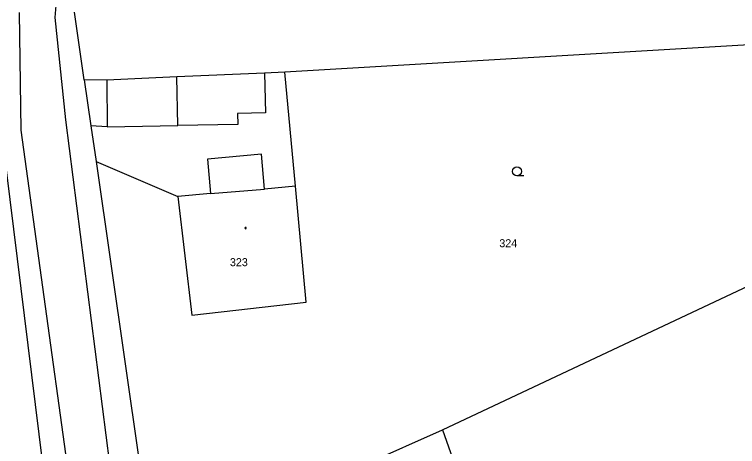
# Model space of a CAD drawing. Extents: x -454285 to -453563, y -1108687 to -1108249.
# Drawn here: x -454141.3 to -454078.1, y -1108501.4 to -1108463.6 of the extents above; entities that cross this region are included whole.
import ezdxf

# ---------------------------------------------------------------- set-up
doc = ezdxf.new("R2010")
doc.units = 0
for name, color, linetype in [('1', 7, 'Continuous'), ('14', 7, 'Continuous'), ('15', 7, 'Continuous'), ('2', 7, 'Continuous'), ('23', 7, 'Continuous'), ('25', 7, 'Continuous')]:
    doc.layers.add(name, color=color, linetype=linetype)

# ---------------------------------------------------------------- blocks, each defined once
blk = doc.blocks.new('Z402')
for start, end in [(0, 180), (180, 0)]:
    blk.add_arc((0, 0), 0.15, start, end)
blk = doc.blocks.new('Z3040')
blk.add_line((1.5, 0), (0, 0))
blk.add_circle((0, 1), 1)

msp = doc.modelspace()

# ---------------------------------------------------------------- linework, layer by layer
at = {"layer": '1'}
for p, q in [((-454135.227, -1108469.281), (-454136.077, -1108463.351)), ((-454059.467, -1108465.161), (-454117.667, -1108468.621)), ((-454119.447, -1108468.701), (-454127.117, -1108469.031)), ((-454117.667, -1108468.621), (-454119.447, -1108468.701)), ((-454116.757, -1108478.601), (-454117.667, -1108468.621)), ((-454133.247, -1108469.301), (-454135.227, -1108469.281)), ((-454135.227, -1108469.281), (-454134.637, -1108473.321)), ((-454127.117, -1108469.031), (-454133.247, -1108469.301)), ((-454134.637, -1108473.321), (-454134.187, -1108476.441)), ((-454137.067, -1108517.391), (-454142.337, -1108474.561)), ((-454134.187, -1108476.441), (-454127.037, -1108479.491)), ((-454134.187, -1108476.441), (-454129.187, -1108511.151)), ((-454115.827, -1108488.751), (-454116.757, -1108478.601)), ((-454127.037, -1108479.491), (-454125.817, -1108489.881)), ((-454103.897, -1108499.911), (-454072.677, -1108485.191)), ((-454125.817, -1108489.881), (-454115.827, -1108488.751)), ((-454129.187, -1108511.151), (-454103.897, -1108499.911)), ((-454103.897, -1108499.911), (-454091.257, -1108535.081))]:
    msp.add_line(p, q, dxfattribs=at)
at = {"layer": '2'}
for p, q in [((-454136.987, -1108453.031), (-454137.787, -1108463.831)), ((-454140.737, -1108473.691), (-454140.887, -1108463.391)), ((-454137.787, -1108463.831), (-454136.867, -1108472.781)), ((-454119.447, -1108468.701), (-454119.377, -1108472.181)), ((-454133.247, -1108469.301), (-454133.207, -1108473.381)), ((-454127.027, -1108473.281), (-454127.117, -1108469.031)), ((-454119.377, -1108472.181), (-454121.817, -1108472.231)), ((-454121.817, -1108472.231), (-454121.797, -1108473.181)), ((-454136.867, -1108472.781), (-454127.047, -1108549.571)), ((-454121.797, -1108473.181), (-454127.027, -1108473.281)), ((-454130.207, -1108549.991), (-454140.737, -1108473.691)), ((-454133.207, -1108473.381), (-454134.637, -1108473.321)), ((-454133.207, -1108473.381), (-454127.027, -1108473.281)), ((-454119.717, -1108475.791), (-454124.447, -1108476.221)), ((-454119.447, -1108478.851), (-454119.717, -1108475.791)), ((-454124.447, -1108476.221), (-454124.167, -1108479.231)), ((-454124.167, -1108479.231), (-454119.447, -1108478.851)), ((-454116.757, -1108478.601), (-454119.447, -1108478.851)), ((-454124.167, -1108479.231), (-454127.037, -1108479.491))]:
    msp.add_line(p, q, dxfattribs=at)

# ---------------------------------------------------------------- block references
at = {"layer": '23', "xscale": 0.4, "yscale": 0.4000000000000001}
msp.add_blockref('Z3040', (-454097.377, -1108477.691), dxfattribs=at)
at = {"layer": '25', "xscale": 0.4, "yscale": 0.4000000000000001}
msp.add_blockref('Z402', (-454121.117, -1108482.261), dxfattribs=at)

# ---------------------------------------------------------------- texts
at = {"layer": '14'}
msp.add_text('324', height=0.7, dxfattribs=at).set_placement((-454098.92, -1108483.931))
at = {"layer": '15'}
msp.add_text('323', height=0.7, dxfattribs=at).set_placement((-454122.48, -1108485.591))

doc.saveas('drawing.dxf')
